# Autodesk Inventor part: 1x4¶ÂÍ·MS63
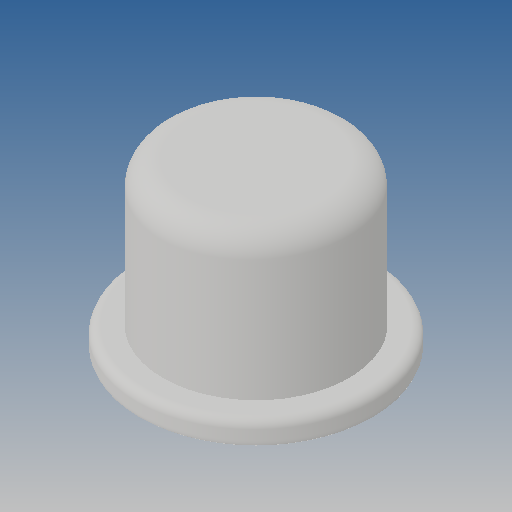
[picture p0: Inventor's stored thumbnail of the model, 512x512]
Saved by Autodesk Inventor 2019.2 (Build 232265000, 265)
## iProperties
Created: 2013-07
Part Number: 1x4¶ÂÍ·MS63
Material: Ogólny
Document SubType Name: Modeling
Designer: CADENGINEERING4
Density: 1 g/cm^3
Appearance: Domyślna
Author: CADENGINEERING4
Revision Number: ÈÎºÎ
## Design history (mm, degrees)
feature "Ô²½Ç1"
node "Bryła1"
